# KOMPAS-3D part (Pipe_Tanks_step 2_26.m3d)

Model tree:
1. X Axis
2. Y Axis
3. Z Axis  (labels: T-Bend Dn 50; Pipe Dn 50)
     Òîëùèíà ñòåíêè 1 = 1

Referenced files in C:\Documents and Settings\kashirsky\Мои документы\Camtasia Studio\Pipelines3D\Tanks\: Tanks_step 2.a3d
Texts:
  Pipe Dn 50
  Steel ASTM A295
  Three Point Plane
  Plane at Angle
  Line and Point Plane
  Axis through Two Vertices
  Axis of Feature
  Axis of Conical Surface
  Axis through Edge
  Trim by Surface
  Trim by Sketch
  Feature with No History
  Intersection Axis of Two Planes
  Two Line Plane
  Line and Face Plane
  Bend by line
  Hole in sheet body
  Cut in sheet body
  Point in CM
  Linear Dimension from Line to Point
  Surface Finish Symbol
  Geometric Tolerance Symbol
  Leader #1
  Leader #2
  Leader #3
  Shape Deviations and Datum
  Node point number
  Mark of coordination axis
  Node point designation
  Mark/Reference designation with leader
  Mark/reference designation on line
  Mark/Reference designation without leader
  T-Bend Dn 50
  Plane of section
